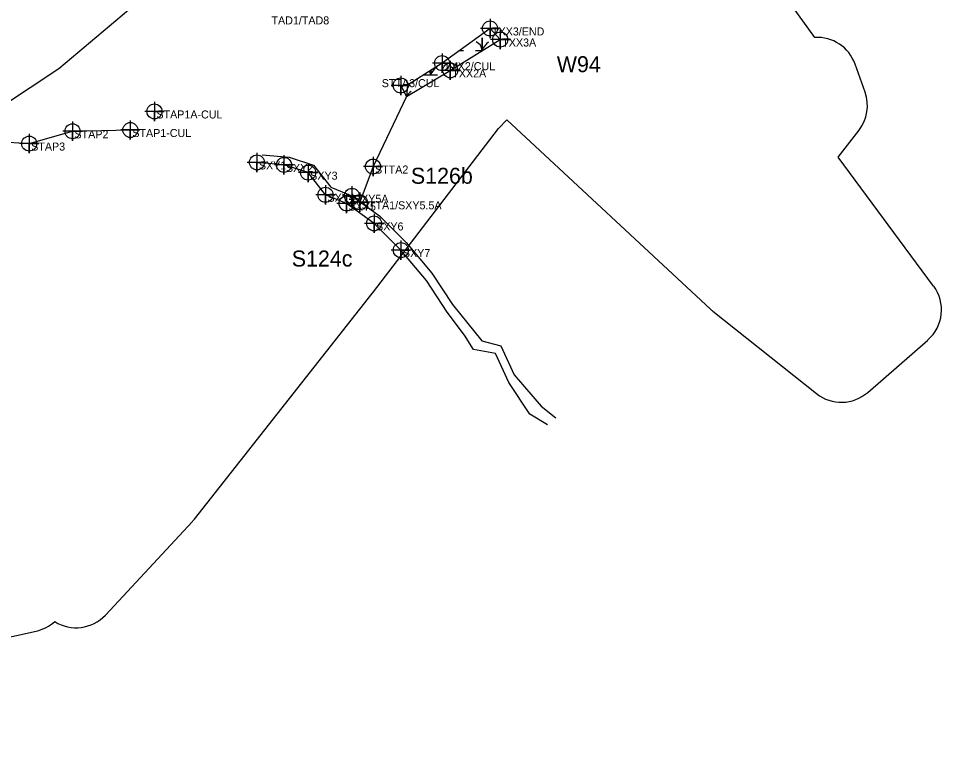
# Model space of a CAD drawing. Extents: x 1253697 to 1278588, y 912189 to 981699.
# Drawn here: x 1267755 to 1268908, y 965404 to 966316 of the extents above; entities that cross this region are included whole.
import ezdxf

# ---------------------------------------------------------------- set-up
doc = ezdxf.new("R2010")
doc.units = 0
for name, color, linetype in [('Default', 7, 'Continuous'), ('Exist Environmental Wetland Boundary', 7, 'Continuous'), ('Exist Environmental Wetland Boundary Cogo Comment', 7, 'Continuous'), ('Exist Environmental Wetland Boundary Cogo Number', 7, 'Continuous'), ('Exist Environmental Wetland Boundary Cogo Point CELL', 7, 'Continuous'), ('Exist Hydro Jurisdictional Stream or Body of Water Mitigable', 7, 'Continuous'), ('Exist Hydro Jurisdictional Stream or Body of Water Mitigable Cogo Comment', 7, 'Continuous'), ('Exist Hydro Jurisdictional Stream or Body of Water Mitigable Cogo Number', 7, 'Continuous'), ('Exist Hydro Jurisdictional Stream or Body of Water Mitigable Cogo Point CELL', 7, 'Continuous'), ('Exist Hydro Swamp or Marsh', 7, 'Continuous')]:
    doc.layers.add(name, color=color, linetype=linetype)

msp = doc.modelspace()

# ---------------------------------------------------------------- linework, layer by layer
at = {"layer": 'Default'}
for p, q in [((1268812.9, 966224.2), (1268800.4, 966259.4)), ((1268812.9, 966224.2), (1268800.4, 966259.4)), ((1267975.4, 965690.9), (1268197.4, 965972.7)), ((1267975.4, 965690.9), (1268197.4, 965972.7)), ((1268622.6, 965950.8), (1268752.1, 965847.7)), ((1268622.6, 965950.8), (1268752.1, 965847.7)), ((1268816.1, 965849.1), (1268891.2, 965914.6)), ((1268816.1, 965849.1), (1268891.2, 965914.6)), ((1267864, 965571), (1267972.7, 965687.8)), ((1267864, 965571), (1267972.7, 965687.8))]:
    msp.add_line(p, q, dxfattribs=at)
for points in [[(1268016.1, 966495.3), (1267901, 966333.2), (1267805.7, 966253.3), (1267446.3, 966015.2)], [(1268016.1, 966495.3), (1267901, 966333.2), (1267805.7, 966253.3), (1267446.3, 966015.2)], [(1268750.1, 966292.5), (1268722.1, 966331.3), (1268720.7, 966351.7)], [(1268750.1, 966292.5), (1268722.1, 966331.3), (1268720.7, 966351.7)], [(1268197.8, 965973.3), (1268354.9, 966179), (1268365.3, 966189.7), (1268619.7, 965953.3)], [(1268197.8, 965973.3), (1268354.9, 966179), (1268365.3, 966189.7), (1268619.7, 965953.3)], [(1268898.5, 965982), (1268779.4, 966143.2), (1268805.4, 966176.9)], [(1268898.5, 965982), (1268779.4, 966143.2), (1268805.4, 966176.9)], [(1267462.1, 965404.2), (1267661.8, 965525.4), (1267777.8, 965550.9)], [(1267462.1, 965404.2), (1267661.8, 965525.4), (1267777.8, 965550.9)]]:
    msp.add_lwpolyline(points, dxfattribs=at)
for centre, start, end in [((1268753.2, 966242.6), 19.5571, 93.6534), ((1268753.2, 966242.6), 19.5571, 93.6534), ((1268765.7, 966207.4), 322.4062, 19.5571), ((1268765.7, 966207.4), 322.4062, 19.5571), ((1268158.1, 966003.7), 321.7735, 322.6224), ((1268158.1, 966003.7), 321.7735, 322.6224), ((1268858.3, 965952.3), 311.0981, 36.4816), ((1268858.3, 965952.3), 311.0981, 36.4816), ((1268653.7, 965989.9), 227.1031, 231.4699), ((1268653.7, 965989.9), 227.1031, 231.4699), ((1268783.3, 965886.8), 231.4699, 311.0981), ((1268783.3, 965886.8), 231.4699, 311.0981), ((1267936.1, 965721.9), 317.0317, 321.7735), ((1267936.1, 965721.9), 317.0317, 321.7735), ((1267827.4, 965605.1), 237.7768, 317.0317), ((1267827.4, 965605.1), 237.7768, 317.0317), ((1267767, 965599.8), 282.4215, 312.3981), ((1267767, 965599.8), 282.4215, 312.3981)]:
    msp.add_arc(centre, 50, start, end, dxfattribs=at)
at = {"layer": 'Exist Environmental Wetland Boundary'}
for points in [[(1268357.2, 966290), (1268344.4, 966303.8), (1268284.5, 966260.5), (1268241.2, 966233.2), (1268240.2, 966218.7)], [(1268240.2, 966218.7), (1268294.8, 966251.5), (1268357.2, 966290)]]:
    msp.add_lwpolyline(points, dxfattribs=at)
at = {"layer": 'Exist Environmental Wetland Boundary Cogo Point CELL'}
for points in [[(1268344.4, 966315.8), (1268344.4, 966291.8), (1268344.4, 966303.8), (1268356.4, 966303.8), (1268332.4, 966303.8)], [(1268357.2, 966302), (1268357.2, 966278), (1268357.2, 966290), (1268369.2, 966290), (1268345.2, 966290)], [(1268284.5, 966272.5), (1268284.5, 966248.5), (1268284.5, 966260.5), (1268296.5, 966260.5), (1268272.5, 966260.5)], [(1268294.8, 966263.5), (1268294.8, 966239.5), (1268294.8, 966251.5), (1268306.8, 966251.5), (1268282.8, 966251.5)]]:
    msp.add_lwpolyline(points, dxfattribs=at)
for centre in [(1268344.4, 966303.8), (1268357.2, 966290), (1268284.5, 966260.5), (1268294.8, 966251.5)]:
    msp.add_circle(centre, 9.38, dxfattribs=at)
at = {"layer": 'Exist Hydro Jurisdictional Stream or Body of Water Mitigable'}
for points in [[(1268232.9, 966232.6), (1268240.2, 966218.7), (1268198.3, 966131.3), (1268181.8, 966086.7)], [(1267671.6, 966164.5), (1267691.2, 966165), (1267768.9, 966160), (1267823, 966175.4), (1267895.2, 966177)], [(1268060, 966146), (1268093.7, 966142.9), (1268123.9, 966133.2), (1268145.5, 966105.6), (1268172, 966094.7), (1268206.3, 966069.8), (1268239.7, 966036.5), (1268271.7, 965998.3), (1268297.6, 965959.1), (1268334.3, 965913.6), (1268357.8, 965907.2), (1268374.7, 965871), (1268408.3, 965831.9), (1268426.5, 965817.5)], [(1268416.2, 965808.6), (1268394.3, 965821.9), (1268368, 965861.5), (1268351.2, 965897.6), (1268323.9, 965902.8), (1268312.4, 965920.8), (1268290.9, 965949.5), (1268265.1, 965988.8), (1268233.1, 966026.9), (1268199.6, 966060.3), (1268165.3, 966085.2), (1268138.9, 966096), (1268117.3, 966123.7), (1268087.1, 966133.4), (1268053.3, 966136.5)]]:
    msp.add_lwpolyline(points, dxfattribs=at)
at = {"layer": 'Exist Hydro Jurisdictional Stream or Body of Water Mitigable Cogo Point CELL'}
for points in [[(1268232.9, 966244.6), (1268232.9, 966220.6), (1268232.9, 966232.6), (1268244.9, 966232.6), (1268220.9, 966232.6)], [(1267925.3, 966212.2), (1267925.3, 966188.2), (1267925.3, 966200.2), (1267937.3, 966200.2), (1267913.3, 966200.2)], [(1267823, 966187.4), (1267823, 966163.4), (1267823, 966175.4), (1267835, 966175.4), (1267811, 966175.4)], [(1267895.2, 966189), (1267895.2, 966165), (1267895.2, 966177), (1267907.2, 966177), (1267883.2, 966177)], [(1267768.9, 966172), (1267768.9, 966148), (1267768.9, 966160), (1267780.9, 966160), (1267756.9, 966160)], [(1268053.3, 966148.5), (1268053.3, 966124.5), (1268053.3, 966136.5), (1268065.3, 966136.5), (1268041.3, 966136.5)], [(1268087.1, 966145.4), (1268087.1, 966121.4), (1268087.1, 966133.4), (1268099.1, 966133.4), (1268075.1, 966133.4)], [(1268117.3, 966135.7), (1268117.3, 966111.7), (1268117.3, 966123.7), (1268129.3, 966123.7), (1268105.3, 966123.7)], [(1268198.3, 966143.3), (1268198.3, 966119.3), (1268198.3, 966131.3), (1268210.3, 966131.3), (1268186.3, 966131.3)], [(1268138.9, 966108), (1268138.9, 966084), (1268138.9, 966096), (1268150.9, 966096), (1268126.9, 966096)], [(1268172, 966106.7), (1268172, 966082.7), (1268172, 966094.7), (1268184, 966094.7), (1268160, 966094.7)], [(1268181.8, 966098.7), (1268181.8, 966074.7), (1268181.8, 966086.7), (1268193.8, 966086.7), (1268169.8, 966086.7)], [(1268165.3, 966097.2), (1268165.3, 966073.2), (1268165.3, 966085.2), (1268177.3, 966085.2), (1268153.3, 966085.2)], [(1268199.6, 966072.3), (1268199.6, 966048.3), (1268199.6, 966060.3), (1268211.6, 966060.3), (1268187.6, 966060.3)], [(1268233.1, 966038.9), (1268233.1, 966014.9), (1268233.1, 966026.9), (1268245.1, 966026.9), (1268221.1, 966026.9)]]:
    msp.add_lwpolyline(points, dxfattribs=at)
for centre in [(1268232.9, 966232.6), (1267925.3, 966200.2), (1267823, 966175.4), (1267895.2, 966177), (1267768.9, 966160), (1268053.3, 966136.5), (1268087.1, 966133.4), (1268117.3, 966123.7), (1268198.3, 966131.3), (1268138.9, 966096), (1268172, 966094.7), (1268165.3, 966085.2), (1268181.8, 966086.7), (1268199.6, 966060.3), (1268233.1, 966026.9)]:
    msp.add_circle(centre, 9.38, dxfattribs=at)
at = {"layer": 'Exist Hydro Swamp or Marsh'}
msp.add_line((1268306.7, 966276.5), (1268311.1, 966276.5), dxfattribs=at)
for points in [[(1268326.1, 966276.5), (1268334.7, 966276.5), (1268334.7, 966292.3), (1268334.7, 966276.5), (1268335.3, 966276.5)], [(1268302.5, 966256.2), (1268302.5, 966261.5), (1268302.5, 966256.2)], [(1268261.7, 966245.7), (1268270.3, 966245.7), (1268270.3, 966251.5)], [(1268270.3, 966251.5), (1268270.3, 966245.7), (1268278.9, 966245.7)]]:
    msp.add_lwpolyline(points, dxfattribs=at)
for centre, radius, start, end in [((1268322.4, 966275.6), 12.3, 4.1403, 67.535), ((1268352.9, 966270.4), 19.2, 122.1274, 161.6222), ((1268258, 966244.8), 12.3, 4.1403, 28.0489), ((1268288.5, 966239.6), 19.2, 122.1274, 161.6222), ((1268290.2, 966244.8), 12.3, 46.8877, 67.535), ((1268256.3, 966208.9), 19.2, 122.1274, 146.7651)]:
    msp.add_arc(centre, radius, start, end, dxfattribs=at)

# ---------------------------------------------------------------- texts
at = {"layer": 'Exist Environmental Wetland Boundary Cogo Comment'}
for s, p in [('TAD1/TAD8', (1268071.5, 966308.9)), ('TXX3/END', (1268346.9, 966295.1)), ('TXX3A', (1268359.7, 966281.3)), ('TXX2/CUL', (1268287, 966251.7)), ('TXX2A', (1268297.3, 966242.7))]:
    msp.add_text(s, height=10, dxfattribs=at).set_placement(p)
at = {"layer": 'Exist Environmental Wetland Boundary Cogo Number'}
msp.add_text('W94', height=20, dxfattribs=at).set_placement((1268427.8, 966249.2))
at = {"layer": 'Exist Hydro Jurisdictional Stream or Body of Water Mitigable Cogo Comment'}
for s, p in [('STTA3/CUL', (1268209.2, 966230.5)), ('STAP1A-CUL', (1267927.8, 966191.4)), ('STAP2', (1267825.5, 966166.6)), ('STAP1-CUL', (1267897.7, 966168.2)), ('STAP3', (1267771.4, 966151.3)), ('SXY1', (1268055.8, 966127.7)), ('SXY2', (1268089.6, 966124.6)), ('SXY3', (1268119.8, 966114.9)), ('STTA2', (1268200.8, 966122.6)), ('SXY4', (1268141.4, 966087.3)), ('SXY5A', (1268174.5, 966086)), ('STTA1/SXY5.5A', (1268184.3, 966077.9)), ('SXY5', (1268167.8, 966076.4)), ('SXY6', (1268202.1, 966051.5)), ('SXY7', (1268235.6, 966018.2))]:
    msp.add_text(s, height=10, dxfattribs=at).set_placement(p)
at = {"layer": 'Exist Hydro Jurisdictional Stream or Body of Water Mitigable Cogo Number'}
for s, p in [('S126b', (1268245.6, 966109.8)), ('S124c', (1268096.8, 966006.4))]:
    msp.add_text(s, height=20, dxfattribs=at).set_placement(p)

doc.saveas('drawing.dxf')
